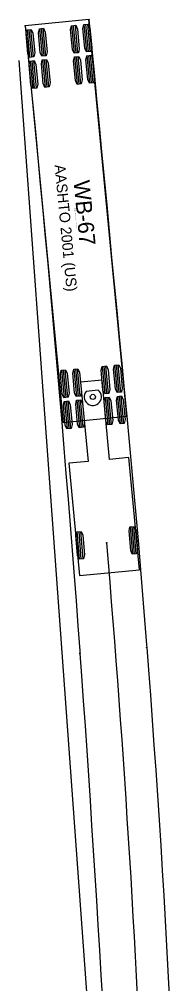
# Model space of a CAD drawing. Extents: x 2131049 to 2132623, y 643184 to 644993.
# Drawn here: x 2131220.8 to 2131240.7, y 643313.3 to 643441.5 of the extents above; entities that cross this region are included whole.
import ezdxf

# ---------------------------------------------------------------- set-up
doc = ezdxf.new("R2010")
doc.units = 0
doc.layers.add('Prop Dimension Text', color=7, linetype='Continuous')
doc.layers.add('Prop EOT', color=7, linetype='Continuous')

msp = doc.modelspace()

# ---------------------------------------------------------------- linework, layer by layer
at = {"layer": 'Prop Dimension Text'}
for p, q in [((2131230.03, 643441.5), (2131221.57, 643440.69)), ((2131229.75, 643437.2), (2131229.4, 643440.85)), ((2131229.98, 643437.23), (2131229.63, 643440.88)), ((2131230.21, 643437.25), (2131229.86, 643440.9)), ((2131235.05, 643388.74), (2131230.03, 643441.5)), ((2131221.57, 643440.69), (2131226.59, 643387.93)), ((2131222.2, 643436.49), (2131221.85, 643440.14)), ((2131222.43, 643436.51), (2131222.08, 643440.16)), ((2131222.66, 643436.53), (2131222.31, 643440.18)), ((2131223.84, 643436.64), (2131223.5, 643440.29)), ((2131224.07, 643436.66), (2131223.72, 643440.31)), ((2131224.3, 643436.69), (2131223.95, 643440.34)), ((2131228.11, 643437.05), (2131227.76, 643440.7)), ((2131228.34, 643437.07), (2131227.99, 643440.72)), ((2131228.56, 643437.09), (2131228.22, 643440.74)), ((2131222.6, 643432.34), (2131222.25, 643435.99)), ((2131222.82, 643432.36), (2131222.48, 643436.01)), ((2131223.05, 643432.38), (2131222.7, 643436.03)), ((2131224.24, 643432.49), (2131223.89, 643436.14)), ((2131224.47, 643432.52), (2131224.12, 643436.17)), ((2131224.69, 643432.54), (2131224.35, 643436.19)), ((2131228.5, 643432.9), (2131228.15, 643436.55)), ((2131228.73, 643432.92), (2131228.38, 643436.57)), ((2131228.96, 643432.94), (2131228.61, 643436.59)), ((2131230.14, 643433.06), (2131229.8, 643436.71)), ((2131230.37, 643433.08), (2131230.03, 643436.73)), ((2131230.6, 643433.1), (2131230.25, 643436.75)), ((2131226.76, 643391.21), (2131226.41, 643394.86)), ((2131226.99, 643391.24), (2131226.64, 643394.89)), ((2131227.22, 643391.26), (2131226.87, 643394.91)), ((2131228.4, 643391.37), (2131228.06, 643395.02)), ((2131228.63, 643391.39), (2131228.28, 643395.04)), ((2131228.86, 643391.41), (2131228.51, 643395.06)), ((2131232.17, 643391.73), (2131231.82, 643395.38)), ((2131232.4, 643391.75), (2131232.05, 643395.4)), ((2131232.63, 643391.77), (2131232.28, 643395.42)), ((2131233.81, 643391.89), (2131233.47, 643395.54)), ((2131234.04, 643391.91), (2131233.69, 643395.56)), ((2131234.27, 643391.93), (2131233.92, 643395.58)), ((2131231.77, 643393.53), (2131228.91, 643393.26)), ((2131232.77, 643383), (2131231.77, 643393.53)), ((2131228.91, 643393.26), (2131229.92, 643382.73)), ((2131231.27, 643392.2), (2131229.66, 643392.05)), ((2131228.8, 643387.22), (2131228.45, 643390.87)), ((2131229.03, 643387.24), (2131228.68, 643390.89)), ((2131229.25, 643387.27), (2131228.91, 643390.92)), ((2131232.56, 643387.58), (2131232.22, 643391.23)), ((2131232.79, 643387.6), (2131232.45, 643391.25)), ((2131233.02, 643387.62), (2131232.67, 643391.27)), ((2131234.21, 643387.74), (2131233.86, 643391.39)), ((2131234.44, 643387.76), (2131234.09, 643391.41)), ((2131234.66, 643387.78), (2131234.32, 643391.43)), ((2131227.16, 643387.07), (2131226.81, 643390.72)), ((2131227.38, 643387.09), (2131227.04, 643390.74)), ((2131227.61, 643387.11), (2131227.26, 643390.76)), ((2131226.59, 643387.93), (2131235.05, 643388.74)), ((2131235.05, 643388.74), (2131235.05, 643388.74)), ((2131235.33, 643383.24), (2131232.77, 643383)), ((2131236.75, 643368.31), (2131235.33, 643383.24)), ((2131229.92, 643382.73), (2131227.36, 643382.48)), ((2131227.36, 643382.48), (2131228.78, 643367.55)), ((2131228.79, 643369.73), (2131228.48, 643373.39)), ((2131229.01, 643369.75), (2131228.71, 643373.41)), ((2131229.24, 643369.77), (2131228.93, 643373.43)), ((2131235.84, 643370.4), (2131235.53, 643374.05)), ((2131236.07, 643370.41), (2131235.76, 643374.07)), ((2131236.3, 643370.43), (2131235.99, 643374.09)), ((2131228.78, 643367.55), (2131236.75, 643368.31)), ((2131236.75, 643368.31), (2131236.75, 643368.31))]:
    msp.add_line(p, q, dxfattribs=at)
for points in [[(2131230.26, 643437.25), (2131229.69, 643437.2), (2131229.47, 643437.69), (2131229.22, 643440.32), (2131229.35, 643440.85), (2131229.91, 643440.9), (2131230.14, 643440.41), (2131230.39, 643437.78)], [(2131222.71, 643436.53), (2131222.14, 643436.48), (2131221.92, 643436.98), (2131221.67, 643439.6), (2131221.8, 643440.13), (2131222.37, 643440.18), (2131222.59, 643439.69), (2131222.84, 643437.06)], [(2131224.36, 643436.69), (2131223.79, 643436.64), (2131223.57, 643437.13), (2131223.32, 643439.76), (2131223.44, 643440.29), (2131224.01, 643440.34), (2131224.23, 643439.85), (2131224.48, 643437.22)], [(2131228.62, 643437.1), (2131228.05, 643437.04), (2131227.83, 643437.54), (2131227.58, 643440.17), (2131227.7, 643440.69), (2131228.27, 643440.75), (2131228.49, 643440.25), (2131228.74, 643437.62)], [(2131223.11, 643432.39), (2131222.54, 643432.33), (2131222.32, 643432.83), (2131222.07, 643435.46), (2131222.19, 643435.98), (2131222.76, 643436.04), (2131222.98, 643435.54), (2131223.23, 643432.91)], [(2131224.75, 643432.54), (2131224.18, 643432.49), (2131223.96, 643432.98), (2131223.71, 643435.61), (2131223.83, 643436.14), (2131224.4, 643436.19), (2131224.62, 643435.7), (2131224.87, 643433.07)], [(2131229.01, 643432.95), (2131228.45, 643432.89), (2131228.23, 643433.39), (2131227.97, 643436.02), (2131228.1, 643436.55), (2131228.67, 643436.6), (2131228.89, 643436.1), (2131229.14, 643433.48)], [(2131230.66, 643433.11), (2131230.09, 643433.05), (2131229.87, 643433.55), (2131229.62, 643436.17), (2131229.74, 643436.7), (2131230.31, 643436.76), (2131230.53, 643436.26), (2131230.78, 643433.63)], [(2131227.27, 643391.26), (2131226.7, 643391.21), (2131226.48, 643391.7), (2131226.23, 643394.33), (2131226.36, 643394.86), (2131226.93, 643394.91), (2131227.15, 643394.42), (2131227.4, 643391.79)], [(2131228.92, 643391.42), (2131228.35, 643391.37), (2131228.13, 643391.86), (2131227.88, 643394.49), (2131228, 643395.02), (2131228.57, 643395.07), (2131228.79, 643394.57), (2131229.04, 643391.95)], [(2131232.68, 643391.78), (2131232.11, 643391.72), (2131231.89, 643392.22), (2131231.64, 643394.85), (2131231.77, 643395.37), (2131232.34, 643395.43), (2131232.56, 643394.93), (2131232.81, 643392.31)], [(2131234.33, 643391.93), (2131233.76, 643391.88), (2131233.54, 643392.37), (2131233.29, 643395), (2131233.41, 643395.53), (2131233.98, 643395.58), (2131234.2, 643395.09), (2131234.45, 643392.46)], [(2131229.31, 643387.27), (2131228.74, 643387.22), (2131228.52, 643387.71), (2131228.27, 643390.34), (2131228.39, 643390.87), (2131228.96, 643390.92), (2131229.18, 643390.43), (2131229.43, 643387.8)], [(2131233.08, 643387.63), (2131232.51, 643387.58), (2131232.29, 643388.07), (2131232.04, 643390.7), (2131232.16, 643391.23), (2131232.73, 643391.28), (2131232.95, 643390.79), (2131233.2, 643388.16)], [(2131234.72, 643387.79), (2131234.15, 643387.73), (2131233.93, 643388.23), (2131233.68, 643390.86), (2131233.8, 643391.38), (2131234.37, 643391.44), (2131234.59, 643390.94), (2131234.84, 643388.31)], [(2131227.67, 643387.12), (2131227.1, 643387.06), (2131226.88, 643387.56), (2131226.63, 643390.18), (2131226.75, 643390.71), (2131227.32, 643390.77), (2131227.54, 643390.27), (2131227.79, 643387.64)], [(2131229.3, 643369.78), (2131228.73, 643369.73), (2131228.52, 643370.23), (2131228.29, 643372.86), (2131228.42, 643373.38), (2131228.99, 643373.43), (2131229.21, 643372.93), (2131229.43, 643370.3)], [(2131236.35, 643370.44), (2131235.78, 643370.39), (2131235.57, 643370.89), (2131235.35, 643373.52), (2131235.47, 643374.04), (2131236.04, 643374.09), (2131236.26, 643373.6), (2131236.48, 643370.96)]]:
    msp.add_lwpolyline(points, close=True, dxfattribs=at)
for points in [[(2131230.03, 643441.5), (2131230.37, 643437.98), (2131230.7, 643434.47), (2131231.04, 643430.95), (2131231.37, 643427.43), (2131231.71, 643423.91), (2131232.04, 643420.4), (2131232.38, 643416.88), (2131232.71, 643413.36), (2131233.04, 643409.84), (2131233.38, 643406.33), (2131233.71, 643402.81), (2131234.05, 643399.29), (2131234.38, 643395.77), (2131234.72, 643392.26), (2131235.05, 643388.74), (2131235.37, 643385.34), (2131235.69, 643381.94), (2131235.99, 643378.53), (2131236.29, 643375.13), (2131236.59, 643371.72), (2131236.87, 643368.32), (2131236.87, 643368.32), (2131237.15, 643364.99), (2131237.42, 643361.66), (2131237.68, 643358.33), (2131237.7, 643357.99)], [(2131221.57, 643440.69), (2131221.9, 643437.18), (2131222.24, 643433.66), (2131222.57, 643430.14), (2131222.91, 643426.63), (2131223.24, 643423.11), (2131223.57, 643419.59), (2131223.9, 643416.07), (2131224.22, 643412.55), (2131224.55, 643409.03), (2131224.87, 643405.52), (2131225.18, 643402), (2131225.5, 643398.48), (2131225.81, 643394.96), (2131226.11, 643391.44), (2131226.41, 643387.92), (2131226.41, 643387.92), (2131226.7, 643384.51), (2131226.98, 643381.11), (2131227.26, 643377.7), (2131227.53, 643374.3), (2131227.8, 643370.89), (2131228.07, 643367.48), (2131228.07, 643367.48), (2131228.32, 643364.17), (2131228.57, 643360.85), (2131228.81, 643357.53), (2131228.83, 643357.2)], [(2131237.7, 643357.99), (2131237.93, 643355), (2131238.18, 643351.66), (2131238.43, 643348.33), (2131238.66, 643345), (2131238.89, 643341.66), (2131239.12, 643338.33), (2131239.34, 643335), (2131239.55, 643331.66), (2131239.75, 643328.33), (2131239.95, 643324.99), (2131240.15, 643321.65), (2131240.34, 643318.32), (2131240.52, 643314.98), (2131240.69, 643311.65), (2131240.74, 643310.64)], [(2131228.83, 643357.2), (2131229.05, 643354.22), (2131229.28, 643350.9), (2131229.51, 643347.58), (2131229.73, 643344.26), (2131229.95, 643340.94), (2131230.17, 643337.62), (2131230.38, 643334.31), (2131230.59, 643330.99), (2131230.8, 643327.67), (2131231.01, 643324.35), (2131231.21, 643321.03), (2131231.42, 643317.71), (2131231.62, 643314.39), (2131231.82, 643311.07), (2131231.88, 643310.07)]]:
    msp.add_lwpolyline(points, dxfattribs=at)
for centre, radius in [((2131230.03, 643441.5), 0.0417), ((2131221.57, 643440.69), 0.0417), ((2131230.54, 643391.32), 0.34), ((2131232.39, 643371.91), 0.0417), ((2131237.7, 643357.99), 0.0417), ((2131237.7, 643357.99), 0.0417), ((2131228.83, 643357.2), 0.0417), ((2131228.83, 643357.2), 0.0417)]:
    msp.add_circle(centre, radius, dxfattribs=at)
for centre, radius, start, end in [((2131230.54, 643391.32), 1.14, 140.4381, 50.4381), ((2129401.11, 643217.16), 1837.81, 2.21079, 4.83014)]:
    msp.add_arc(centre, radius, start, end, dxfattribs=at)
at = {"layer": 'Prop EOT'}
msp.add_line((2131231.88, 643282.85), (2131220.78, 643436.04), dxfattribs=at)

# ---------------------------------------------------------------- texts
at = {"layer": 'Prop Dimension Text'}
for s, height, p in [('AASHTO 2001 (US)', 1.4167, (2131225.46, 643422.15)), ('WB-67', 2.125, (2131227.98, 643420.02)), ('(c) 2015 Transoft Solutions, Inc. All rights reserved.', 0.085, (2131228.11, 643416.44))]:
    msp.add_text(s, height=height, rotation=275.4381, dxfattribs=at).set_placement(p)

doc.saveas('drawing.dxf')
